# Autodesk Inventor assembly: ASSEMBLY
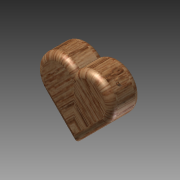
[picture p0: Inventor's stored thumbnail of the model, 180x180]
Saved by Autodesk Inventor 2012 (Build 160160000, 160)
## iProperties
Created: 2011-01
Part Number: ASSEMBLY
Document SubType Name: Assembly
Designer: Microsoft
Author: Microsoft
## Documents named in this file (6)
- C:\Users\David\Desktop\Playground\3D work\Locket\ASSEMBLY.iam
- C:\Users\David\Desktop\Playground\3D work\Locket\BASE2-TOP.ipt
- C:\Users\David\Desktop\Playground\3D work\Locket\BASE2.ipt
- C:\Users\David\Desktop\Playground\3D work\Locket\TOP2.ipt
- C:\Users\David\Desktop\Playground\3D work\Locket\BASE1.ipt
- C:\Users\David\Desktop\Playground\3D work\Locket\TOP1.ipt
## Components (5 placed, 5 different names)
1. BASE2-TOP:1 — Mate:10, Mate:11, Mate:12, Mate:13
2. BASE2:1 — Mate:7, Mate:8, Mate:9, Mate:12
3. TOP2:1 — Mate:3, Mate:7, Angle:1, Mate:13
4. BASE1:1 — Mate:1, Mate:2, Mate:8, Mate:9, Mate:10, Mate:11, Angle:2
5. TOP1:1 — Mate:1, Mate:2, Mate:3, Angle:1, Angle:2
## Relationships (12: Mate 10, Angle 2)
- Mate:1: BASE1:1 ↔ TOP1:1
- Mate:2: BASE1:1 ↔ TOP1:1
- Mate:3: TOP2:1 ↔ TOP1:1
- Mate:7: BASE2:1 ↔ TOP2:1
- Mate:8: BASE2:1 ↔ BASE1:1
- Mate:9: BASE2:1 ↔ BASE1:1
- Angle:1: TOP2:1 ↔ TOP1:1
- Mate:10: BASE2-TOP:1 ↔ BASE1:1
- Mate:11: BASE2-TOP:1 ↔ BASE1:1
- Mate:12: BASE2-TOP:1 ↔ BASE2:1
- Mate:13: BASE2-TOP:1 ↔ TOP2:1
- Angle:2: BASE1:1 ↔ TOP1:1
